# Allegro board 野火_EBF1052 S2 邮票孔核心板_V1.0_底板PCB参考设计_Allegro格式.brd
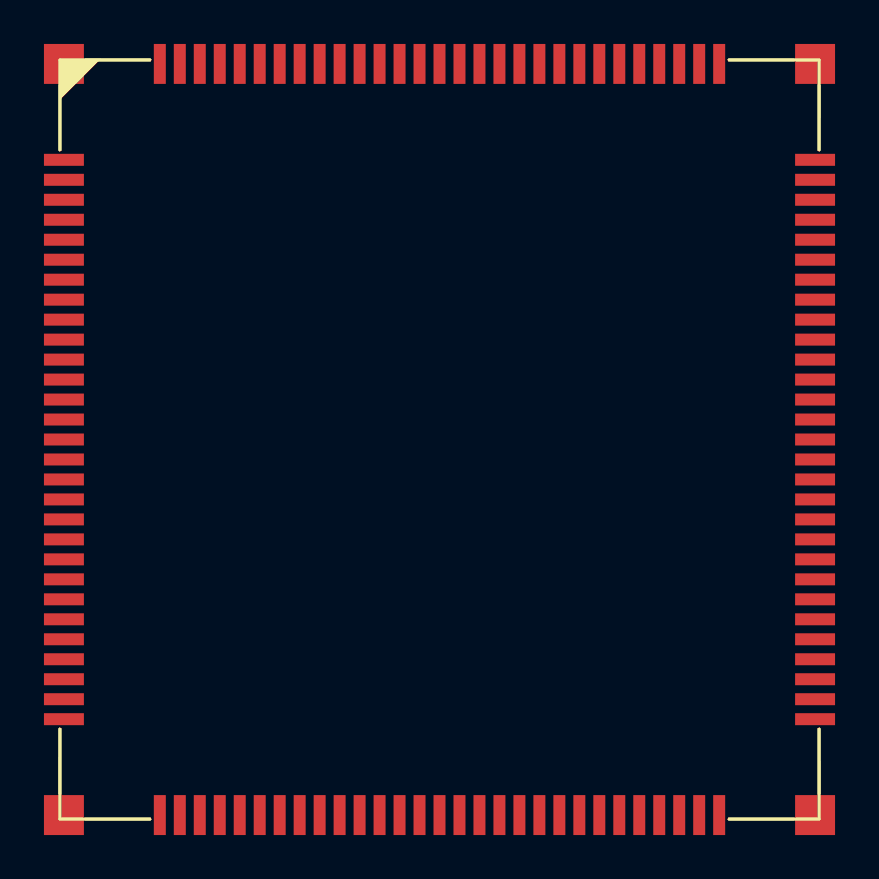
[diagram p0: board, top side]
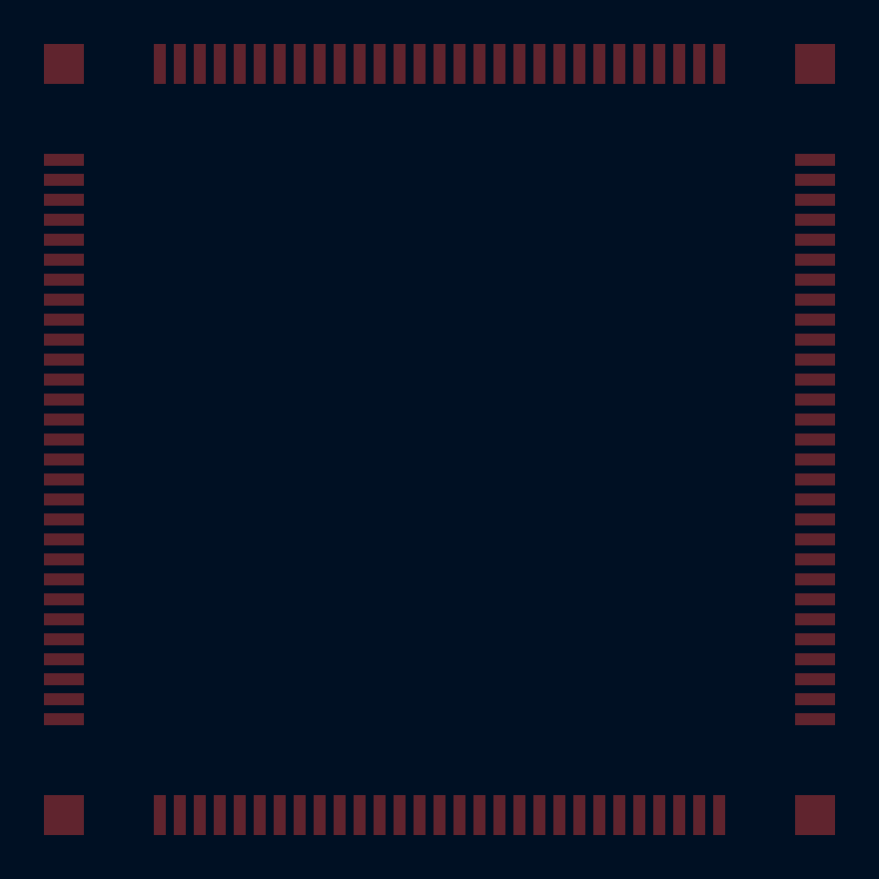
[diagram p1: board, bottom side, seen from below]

No outline. copper layers: TOP, BOTTOM. Coordinates in mm from the lowest, leftmost part position.

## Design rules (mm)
net group CLK1_OUT: nets CLK1_OUT_N CLK1_OUT_P
net group DIFFPAIR0: nets N101529961 N101529971
net group ETH_RX: nets ETH_RXN ETH_RXP
net group ETH_TX: nets ETH_TXN ETH_TXP
net group OTG1_D: nets OTG1_DN OTG1_DP
net group OTG2_D: nets OTG2_DN OTG2_DP

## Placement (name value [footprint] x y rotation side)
U11  rt1052_core_p120  [RT1052_SOM_S2_116P_38X38]  0 0 90 top

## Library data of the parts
U11 = rt1052_core_p120_1

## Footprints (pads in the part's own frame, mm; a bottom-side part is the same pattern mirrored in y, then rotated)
RT1052_SOM_S2_116P_38X38
  rect 0.6x2 smd: 1(14,19) 2(13,19) 3(12,19) 4(11,19) 5(10,19) 6(9,19) 7(8,19) 8(7,19) 9(6,19) 10(5,19) 11(4,19) 12(3,19) 13(2,19) 14(1,19) 15(0,19) 16(-1,19) 17(-2,19) 18(-3,19) 19(-4,19) 20(-5,19) 21(-6,19) 22(-7,19) 23(-8,19) 24(-9,19) 25(-10,19) 26(-11,19) 27(-12,19) 28(-13,19) 29(-14,19) 59(-14,-19) 60(-13,-19) 61(-12,-19) 62(-11,-19) 63(-10,-19) 64(-9,-19) 65(-8,-19) 66(-7,-19) 67(-6,-19) 68(-5,-19) 69(-4,-19) 70(-3,-19) 71(-2,-19) 72(-1,-19) 73(0,-19) 74(1,-19) 75(2,-19) 76(3,-19) 77(4,-19) 78(5,-19) 79(6,-19) 80(7,-19) 81(8,-19) 82(9,-19) 83(10,-19) 84(11,-19) 85(12,-19) 86(13,-19) 87(14,-19)
  rect 2x0.6 smd: 30(-19,14) 31(-19,13) 32(-19,12) 33(-19,11) 34(-19,10) 35(-19,9) 36(-19,8) 37(-19,7) 38(-19,6) 39(-19,5) 40(-19,4) 41(-19,3) 42(-19,2) 43(-19,1) 44(-19,0) 45(-19,-1) 46(-19,-2) 47(-19,-3) 48(-19,-4) 49(-19,-5) 50(-19,-6) 51(-19,-7) 52(-19,-8) 53(-19,-9) 54(-19,-10) 55(-19,-11) 56(-19,-12) 57(-19,-13) 58(-19,-14) 88(19,-14) 89(19,-13) 90(19,-12) 91(19,-11) 92(19,-10) 93(19,-9) 94(19,-8) 95(19,-7) 96(19,-6) 97(19,-5) 98(19,-4) 99(19,-3) 100(19,-2) 101(19,-1) 102(19,0) 103(19,1) 104(19,2) 105(19,3) 106(19,4) 107(19,5) 108(19,6) 109(19,7) 110(19,8) 111(19,9) 112(19,10) 113(19,11) 114(19,12) 115(19,13) 116(19,14)
  rect 2x2 smd: 117(18.8,18.8) 118(-18.8,18.8) 119(-18.8,-18.8) 120(18.8,-18.8)

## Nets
5V_SYS: U11.83(USB_OTG2_VBUS) U11.87(USB_OTG1_VBUS)
GND: U11.28(GND5) U11.30(GND6) U11.37(GND7) U11.44(GND8) U11.51(GND9) U11.58(GND10) U11.66(GND11) U11.74(GND12) U11.80(GND13) U11.84(GND14) U11.88(GND15) U11.109(GND16) U11.110(GND17) U11.111(GND18) U11.112(GND19) U11.117(GND1) U11.118(GND2) U11.119(GND3) U11.120(GND4)
VDD_SNVS_IN: U11.116(VDD_SNVS_3V3)
CAN2_RX: U11.93(GPIO_AD_B0_15/FLEXCAN2_RX)
CAN2_TX: U11.94(GPIO_AD_B0_14/FLEXCAN2_TX)
CLK1_OUT_N: U11.65(CLK1_OUT_N)
CLK1_OUT_P: U11.64(CLK1_OUT_P)
DCDC_3V3: U11.113(3V3_SYS3) U11.114(3V3_SYS2) U11.115(3V3_SYS1)
ENET_CRS_DV: U11.6(GPIO_B1_06/ENET_RX_EN)
ENET_MDC: U11.79(GPIO_AD_B1_04/ENET_MDC)
ENET_MDIO: U11.34(GPIO_B1_15/ENET_MDIO)
ENET_RXD0: U11.8(GPIO_B1_04/ENET_RX_DATA00)
ENET_RXD1: U11.7(GPIO_B1_05/ENET_RX_DATA01)
ENET_RXER: U11.1(GPIO_B1_11/ENET_RX_ER)
ENET_TX_CLK: U11.2(GPIO_B1_10/ENET_TX_CLK)
ENET_TXD0: U11.5(GPIO_B1_07/ENET_TX_DATA00)
ENET_TXD1: U11.4(GPIO_B1_08/ENET_TX_DATA01)
ENET_TXEN: U11.3(GPIO_B1_09/ENET_TX_EN)
FLEXSPI_CLK: U11.53(GPIO_SD_B1_07/FLEXSPIA_SCLK)
FLEXSPI_CLK_B: U11.49(GPIO_SD_B1_04/USDHC2_CLK)
FLEXSPI_D0_A: U11.54(GPIO_SD_B1_08/FLEXSPIA_DATA00)
FLEXSPI_D0_B: U11.48(GPIO_SD_B1_03/USDHC2_DATA0)
FLEXSPI_D1_A: U11.55(GPIO_SD_B1_09/FLEXSPIA_DATA01)
FLEXSPI_D1_B: U11.47(GPIO_SD_B1_02/USDHC2_DATA1)
FLEXSPI_D2_A: U11.56(GPIO_SD_B1_10/FLEXSPIA_DATA02)
FLEXSPI_D2_B: U11.46(GPIO_SD_B1_01/USDHC2_DATA2)
FLEXSPI_D3_A: U11.57(GPIO_SD_B1_11/FLEXSPIA_DATA03)
FLEXSPI_D3_B: U11.45(GPIO_SD_B1_00/USDHC2_DATA3)
FLEXSPI_DQS: U11.50(GPIO_SD_B1_05/USDHC2_CMD)
FLEXSPI_SS0: U11.52(GPIO_SD_B1_06/FLEXSPIA_SS0_B)
GPIO_AD_B0_02: U11.106(GPIO_AD_B0_02/GPIO1_IO02)
GPIO_AD_B0_03: U11.105(GPIO_AD_B0_03/GPIO1_IO03)
GPIO_AD_B0_04: U11.104(GPIO_AD_B0_04/GPIO1_IO04)
GPIO_AD_B0_05: U11.103(GPIO_AD_B0_05/GPIO1_IO05)
GPIO_AD_B1_05: U11.78(GPIO_AD_B1_05/CSI_MCLK)
GPIO_AD_B1_06: U11.77(GPIO_AD_B1_06/CSI_VSYNC)
GPIO_AD_B1_07: U11.76(GPIO_AD_B1_07/CSI_HSYNC)
GPIO_AD_B1_08: U11.75(GPIO_AD_B1_08/CSI_DATA09)
I2C1_SCL: U11.92(GPIO_AD_B1_00/LPI2C1_SCL)
I2C1_SDA: U11.91(GPIO_AD_B1_01/LPI2C1_SDA)
JTAG_NTRST: U11.97(GPIO_AD_B0_11/GPIO1_IO11)
JTAG_TCK: U11.101(JTAG_TCK)
JTAG_TDI: U11.99(GPIO_AD_B0_09/GPIO1_IO09)
JTAG_TDO: U11.98(GPIO_AD_B0_10/GPIO1_IO10)
JTAG_TMS: U11.102(JTAG_TMS)
KEY: U11.63(GPIO5_IO00/KEY)
LCDIF_CLK: U11.29(GPIO_B0_00/LCD_CLK)
LCDIF_D0: U11.24(GPIO_B0_04/LCD_DATA00 (B3))
LCDIF_D1: U11.23(GPIO_B0_05/LCD_DATA01 (B4))
LCDIF_D2: U11.22(GPIO_B0_06/LCD_DATA02 (B5))
LCDIF_D3: U11.21(GPIO_B0_07/LCD_DATA03 (B6))
LCDIF_D4: U11.20(GPIO_B0_08/LCD_DATA04 (B7))
LCDIF_D5: U11.19(GPIO_B0_09/LCD_DATA05 (G2))
LCDIF_D6: U11.18(GPIO_B0_10/LCD_DATA06 (G3))
LCDIF_D7: U11.17(GPIO_B0_11/LCD_DATA07 (G4))
LCDIF_D8: U11.16(GPIO_B0_12/LCD_DATA08 (G5))
LCDIF_D9: U11.15(GPIO_B0_13/LCD_DATA09 (G6))
LCDIF_D10: U11.14(GPIO_B0_14/LCD_DATA10 (G7))
LCDIF_D11: U11.13(GPIO_B0_15/LCD_DATA11 (R3))
LCDIF_D12: U11.12(GPIO_B1_00/LCD_DATA12 (R4))
LCDIF_D13: U11.11(GPIO_B1_01/LCD_DATA13 (R5))
LCDIF_D14: U11.10(GPIO_B1_02/LCD_DATA14 (R6))
LCDIF_D15: U11.9(GPIO_B1_03/LCD_DATA15 (R7))
LCDIF_ENA: U11.27(GPIO_B0_01/LCD_ENABLE)
LCDIF_HS: U11.26(GPIO_B0_02/LCD_HSYNC)
LCDIF_VS: U11.25(GPIO_B0_03/LCD_VSYNC)
ONOFF: U11.59(ONOFF)
OTG1_DN: U11.85(OTG1_DN)
OTG1_DP: U11.86(OTG1_DP)
OTG2_DN: U11.81(OTG2_DN)
OTG2_DP: U11.82(OTG2_DP)
PMIC_ON: U11.60(CCM_PMIC_ON_REQ)
PMIC_STBY: U11.61(CCM_PMIC_VSTBY_REQ)
POR_B: U11.62(SRC_POR_B)
SAI1_MCLK: U11.73(GPIO_AD_B1_09/SAI1_MCLK)
SAI1_RX_BCLK: U11.71(GPIO_AD_B1_11/SAI1_RX_BCLK)
SAI1_RX_SYNC: U11.72(GPIO_AD_B1_10/SAI1_RX_SYNC)
SAI1_RXD: U11.70(GPIO_AD_B1_12/SAI1_RX_DATA00)
SAI1_TX_BCLK: U11.68(GPIO_AD_B1_14/SAI1_TX_BCLK)
SAI1_TX_SYNC: U11.67(GPIO_AD_B1_15/SAI1_TX_SYNC)
SAI1_TXD: U11.69(GPIO_AD_B1_13/SAI1_TX_DATA00)
SD0_VSELECT: U11.33(GPIO_B1_14/SD0_VSELECT)
SD1_CLK: U11.39(GPIO_SD_B0_01/USDHC1_CLK)
SD1_CMD: U11.38(GPIO_SD_B0_00/USDHC1_CMD)
SD1_D0: U11.40(GPIO_SD_B0_02/USDHC1_DATA0)
SD1_D1: U11.41(GPIO_SD_B0_03/USDHC1_DATA1)
SD1_D2: U11.42(GPIO_SD_B0_04/USDHC1_DATA2)
SD1_D3: U11.43(GPIO_SD_B0_05/USDHC1_DATA3)
SEMC_CSX0: U11.36(GPIO_EMC_41)
SEMC_RDY: U11.35(GPIO_EMC_40)
SPDIF_IN: U11.89(GPIO_AD_B1_03/LPUART2_RX)
SPDIF_OUT: U11.90(GPIO_AD_B1_02/LPUART2_TX)
UART1_RXD: U11.95(GPIO_AD_B0_13/LPUART1_RX)
UART1_TXD: U11.96(GPIO_AD_B0_12/LPUART1_TX)
UART5_RXD: U11.32(GPIO_B1_13/LPUART5_RX)
UART5_TXD: U11.31(GPIO_B1_12/LPUART5_TX)
USB_OTG1_ID: U11.108(GPIO_AD_B0_01/USB_OTG1_ID)
USB_OTG2_ID: U11.107(GPIO_AD_B0_00/USB_OTG2_ID)

Pads without a net: U11 100
